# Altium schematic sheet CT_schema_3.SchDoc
size 521 x 498 mm
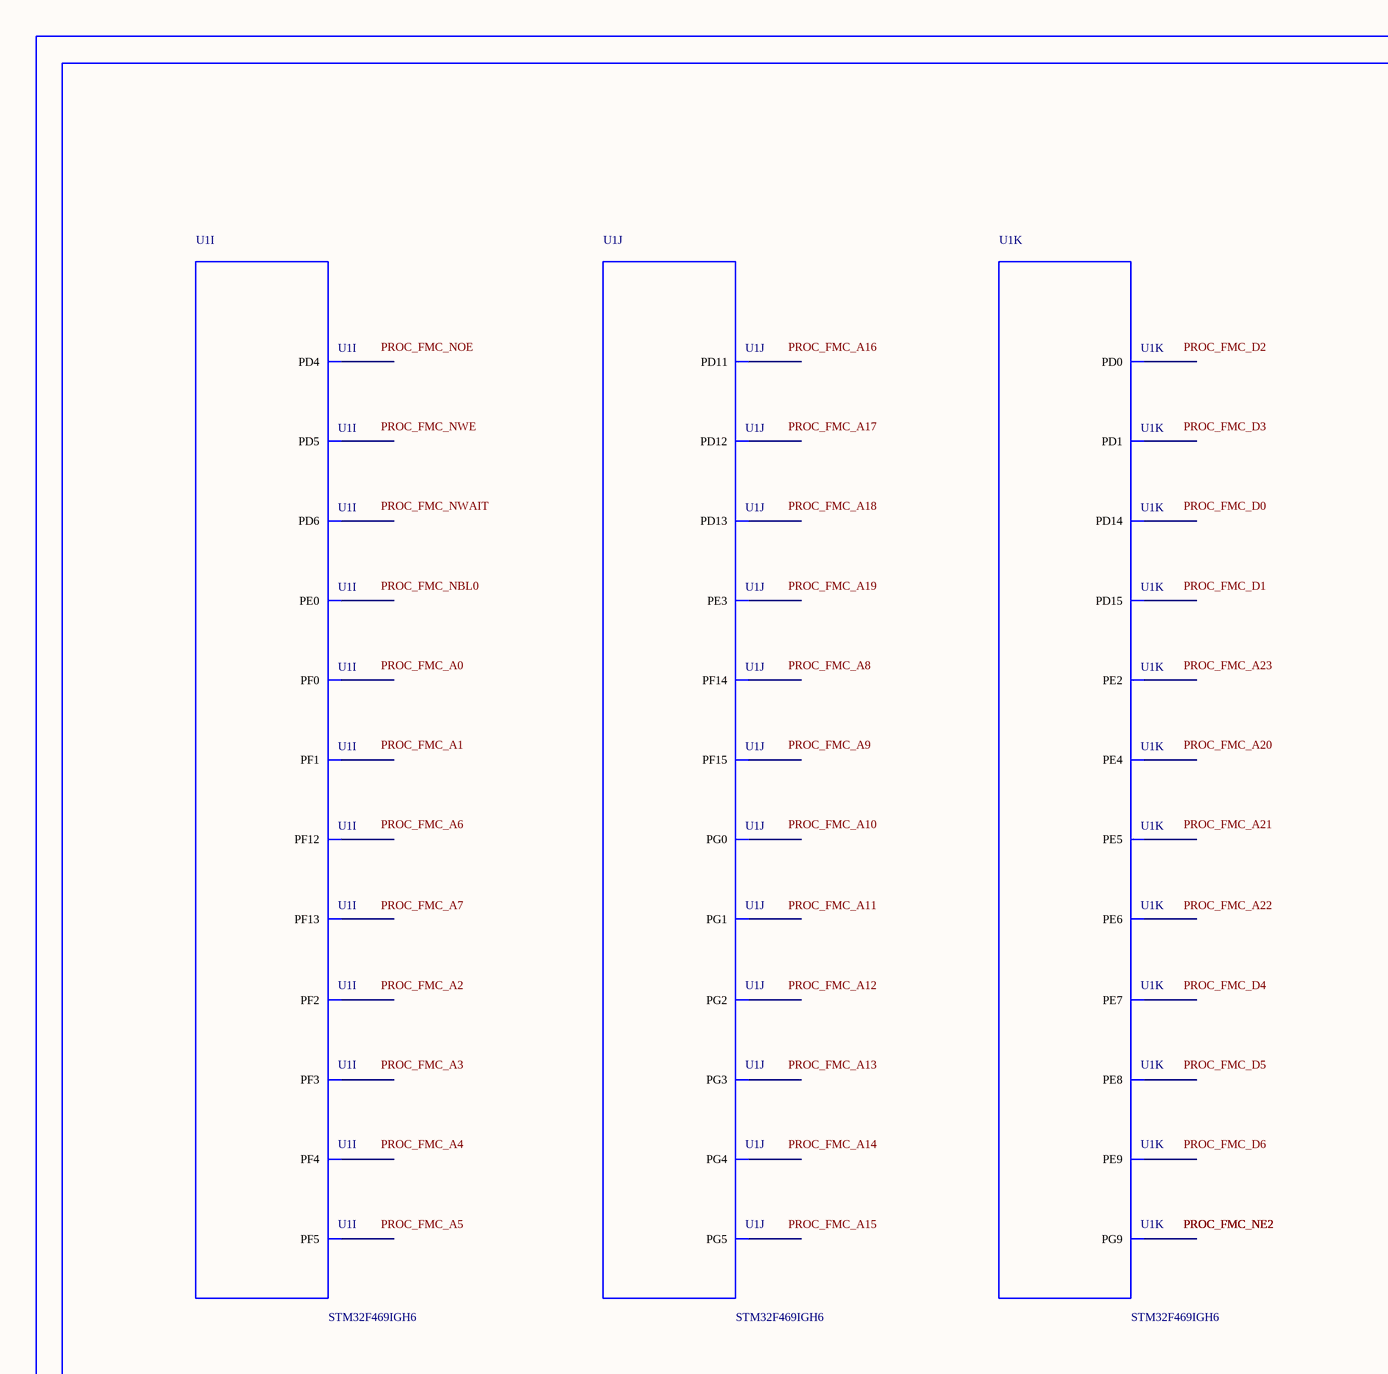
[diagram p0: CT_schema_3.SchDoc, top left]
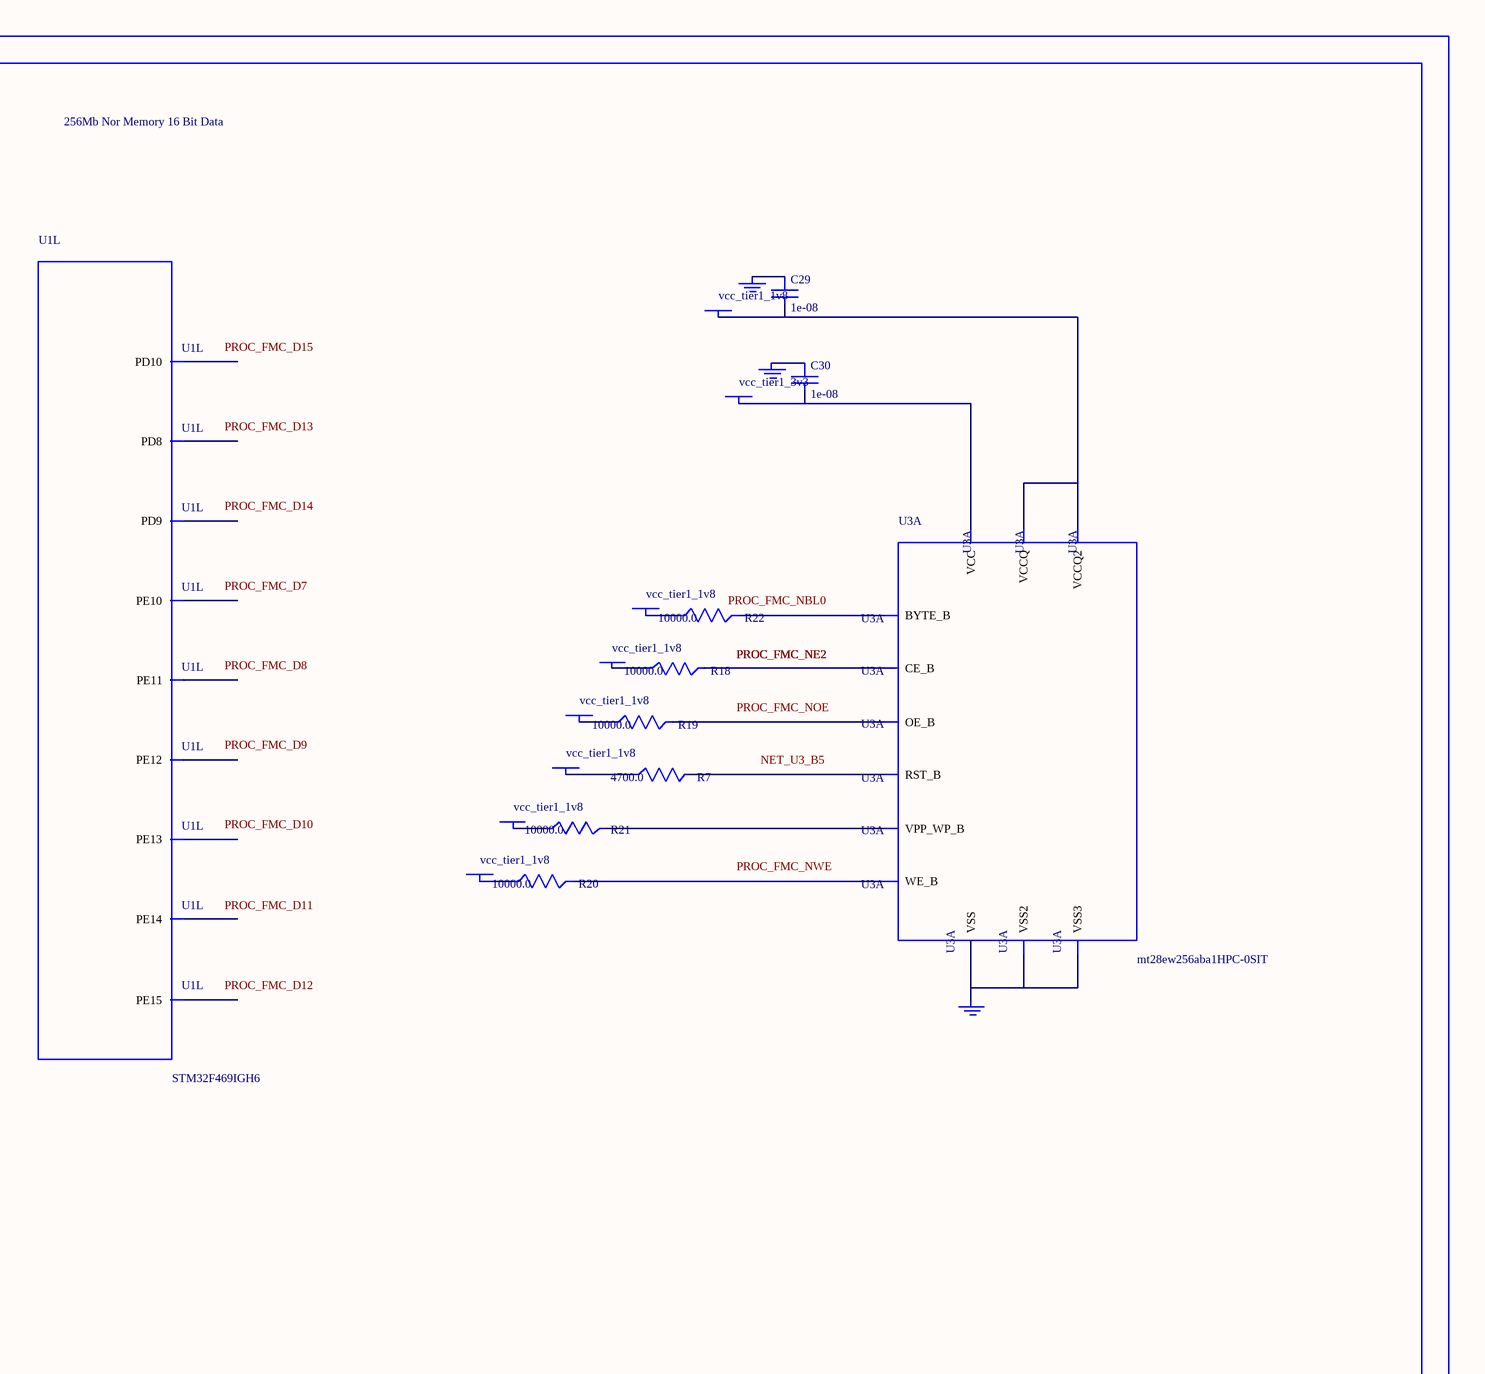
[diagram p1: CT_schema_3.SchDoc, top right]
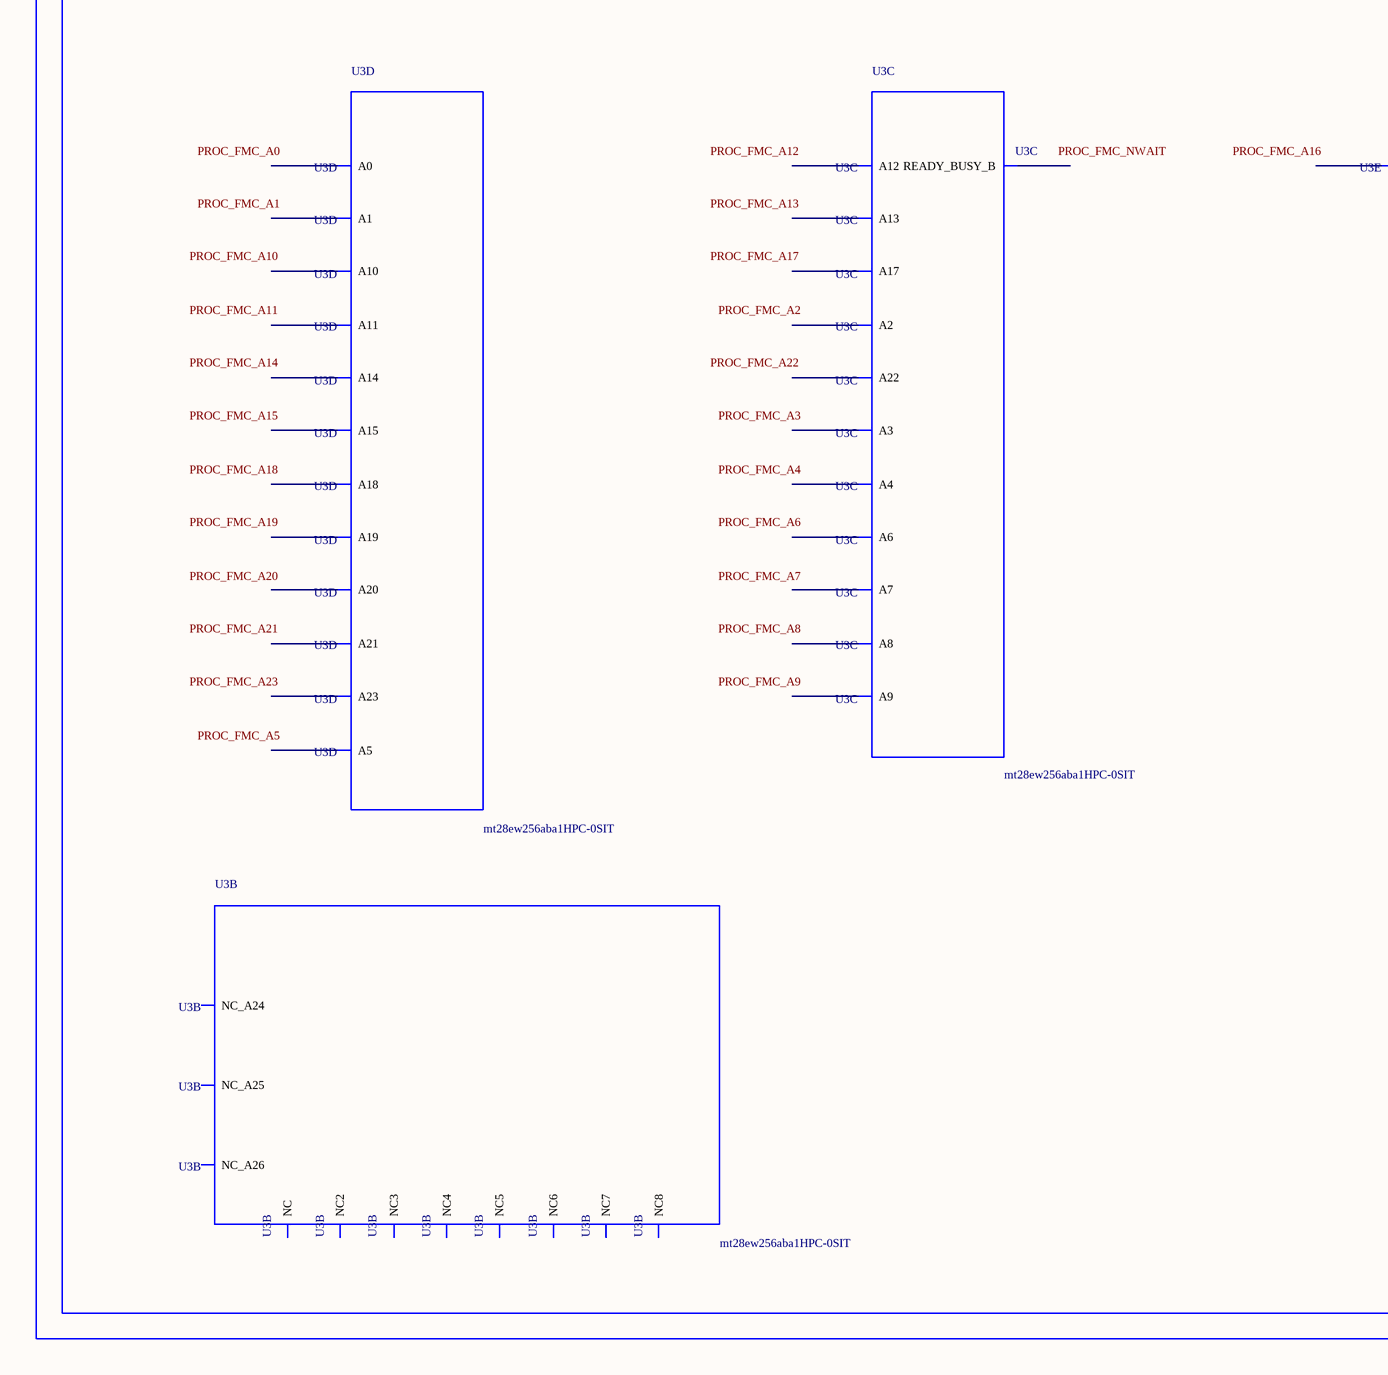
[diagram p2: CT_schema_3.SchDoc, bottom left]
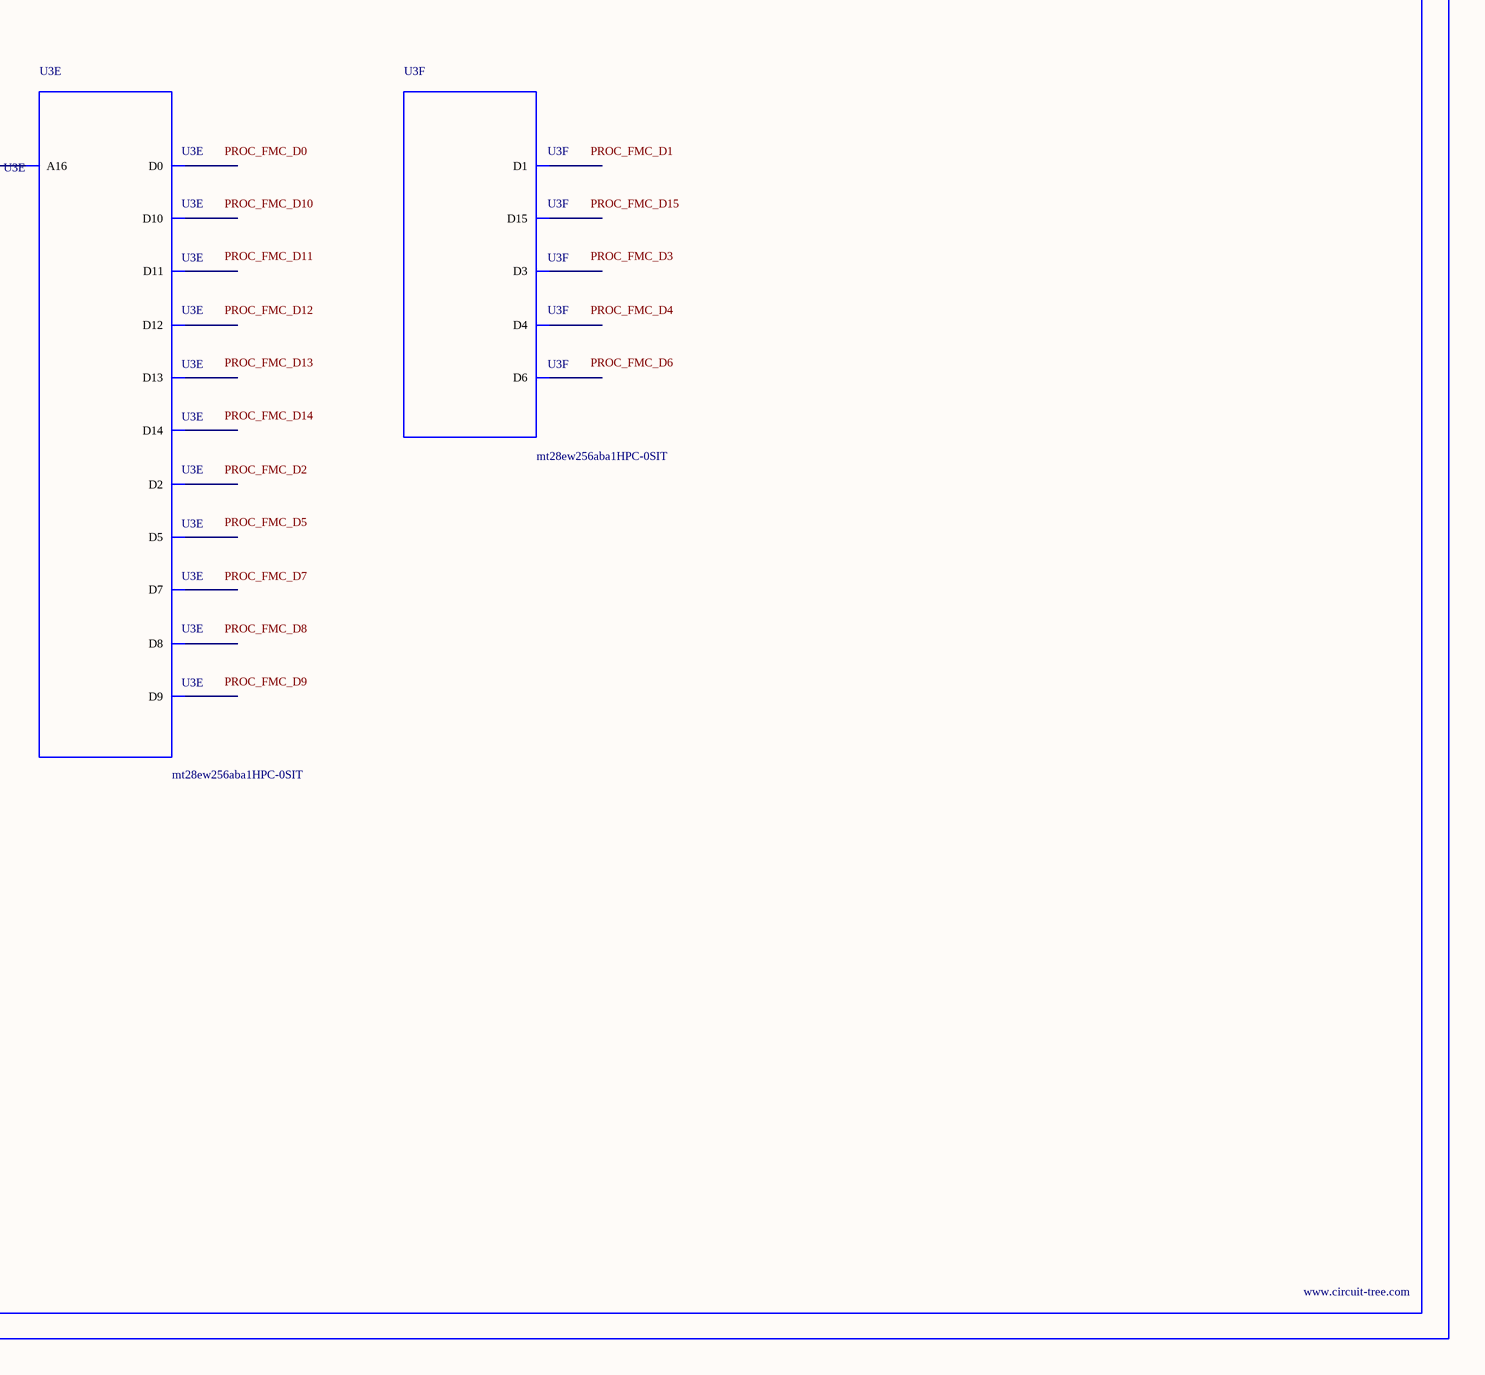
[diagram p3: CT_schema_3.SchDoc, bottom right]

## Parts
BORDER2  (no value)
C29  1e-08  [C0402]
C30  1e-08  [C0402]
GND_INSTANCE_2_0  (no value)
GND_INSTANCE_2_1  (no value)
GND_INSTANCE_2_2  (no value)
POWER_INSTANCE_2_0  vcc_tier1_1v8
POWER_INSTANCE_2_1  vcc_tier1_3v3
POWER_INSTANCE_2_2  vcc_tier1_1v8
POWER_INSTANCE_2_3  vcc_tier1_1v8
POWER_INSTANCE_2_4  vcc_tier1_1v8
POWER_INSTANCE_2_5  vcc_tier1_1v8
POWER_INSTANCE_2_6  vcc_tier1_1v8
POWER_INSTANCE_2_7  vcc_tier1_1v8
R7  4700.0  [R0603]
R18  10000.0  [R0603]
R19  10000.0  [R0603]
R20  10000.0  [R0603]
R21  10000.0  [R0603]
R22  10000.0  [R0603]
U1  STM32F469IGH6  [UFBGA176]  (parts I,J,K,L of 16)
U3  mt28ew256aba1HPC-0SIT  [LBGA-64]  (parts A,B,C,D,E,F of 6)

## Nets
NetC29_1: C29.1 GND_INSTANCE_2_0.0(GND)
NetC29_2: C29.2 POWER_INSTANCE_2_0.0(PWR) U3.D8(VCCQ) U3.F1(VCCQ2)
NetC30_1: C30.1 GND_INSTANCE_2_1.0(GND)
NetC30_2: C30.2 POWER_INSTANCE_2_1.0(PWR) U3.G5(VCC)
NetGND_INSTANCE_2_2_0: GND_INSTANCE_2_2.0(GND) U3.E8(VSS) U3.H2(VSS2) U3.H7(VSS3)
NetPOWER_INSTANCE_2_2_0: POWER_INSTANCE_2_2.0(PWR) R18.1
NetPOWER_INSTANCE_2_3_0: POWER_INSTANCE_2_3.0(PWR) R19.1
NetPOWER_INSTANCE_2_4_0: POWER_INSTANCE_2_4.0(PWR) R20.1
NetPOWER_INSTANCE_2_5_0: POWER_INSTANCE_2_5.0(PWR) R21.1
NetPOWER_INSTANCE_2_6_0: POWER_INSTANCE_2_6.0(PWR) R22.1
NetPOWER_INSTANCE_2_7_0: POWER_INSTANCE_2_7.0(PWR) R7.1
NetR7_2: R7.2 U3.B5(RST_B)
NetR18_2: R18.2 U3.F2(CE_B)
NetR19_2: R19.2 U3.G2(OE_B)
NetR20_2: R20.2 U3.A5(WE_B)
NetR21_2: R21.2 U3.B4(VPP_WP_B)
NetR22_2: R22.2 U3.F7(BYTE_B)

Not connected (* = marked no-connect by the designer): U1 A1(PE3) A2(PE2) A4(PE0) B1(PE4) B2(PE5) B3(PE6) B11(PD6) B12(PD0) C10(PG9) C11(PD5) C12(PD1) D10(PD4) E2(PF0) H2(PF2) H3(PF1) J2(PF3) J3(PF4) K3(PF5) K13(PG5) K14(PG4) K15(PG3) L14(PD15) L15(PG2) M7(PG1) M14(PD14) M15(PD13) N6(PF13) N7(PG0) N11(PE13) N13(PD12) N14(PD11) N15(PD10) P6(PF12) P7(PF15) P8(PE8) P9(PE9) P10(PE11) P11(PE14) P14(PD9) P15(PD8) R7(PF14) R8(PE7) R9(PE10) R10(PE12) R11(PE15); U3 A1(NC) A2(A3) A3(A7) A4(READY_BUSY_B) A6(A9) A7(A13) A8(NC2) B1(NC_A26) B2(A4) B3(A17) B6(A8) B7(A12) B8(A22) C1(NC3) C2(A2) C3(A6) C4(A18) C5(A21) C6(A10) C7(A14) C8(A23) D1(NC4) D2(A1) D3(A5) D4(A20) D5(A19) D6(A11) D7(A15) E1(NC5) E2(A0) E3(D0) E4(D2) E5(D5) E6(D7) E7(A16) F3(D8) F4(D10) F5(D12) F6(D14) F8(NC_A24) G1(NC6) G3(D9) G4(D11) G6(D13) G7(D15) G8(NC_A25) H1(NC7) H3(D1) H4(D3) H5(D4) H6(D6) H8(NC8)

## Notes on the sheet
- Labels drawn without touching a wire or pin: NET_U3_B5, PROC_FMC_A0, PROC_FMC_A1, PROC_FMC_A2, PROC_FMC_A3, PROC_FMC_A4, PROC_FMC_A5, PROC_FMC_A6, PROC_FMC_A7, PROC_FMC_A8, PROC_FMC_A9, PROC_FMC_A10, PROC_FMC_A11, PROC_FMC_A12, PROC_FMC_A13, PROC_FMC_A14, PROC_FMC_A15, PROC_FMC_A16, PROC_FMC_A17, PROC_FMC_A18, PROC_FMC_A19, PROC_FMC_A20, PROC_FMC_A21, PROC_FMC_A22, PROC_FMC_A23, PROC_FMC_D0, PROC_FMC_D1, PROC_FMC_D2, PROC_FMC_D3, PROC_FMC_D4, PROC_FMC_D5, PROC_FMC_D6, PROC_FMC_D7, PROC_FMC_D8, PROC_FMC_D9, PROC_FMC_D10, PROC_FMC_D11, PROC_FMC_D12, PROC_FMC_D13, PROC_FMC_D14, PROC_FMC_D15, PROC_FMC_NBL0, PROC_FMC_NOE, PROC_FMC_NWAIT, PROC_FMC_NWE

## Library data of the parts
BORDER2 = BORDER_PAGE2
C29 C30 = C0402C103K3RAC
GND_INSTANCE_2_0-GND_INSTANCE_2_2 = GND
POWER_INSTANCE_2_0-POWER_INSTANCE_2_7 = PWR
R7 = RC0603JR-074K7L
R18-R22 = RC0603JR-0710KL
